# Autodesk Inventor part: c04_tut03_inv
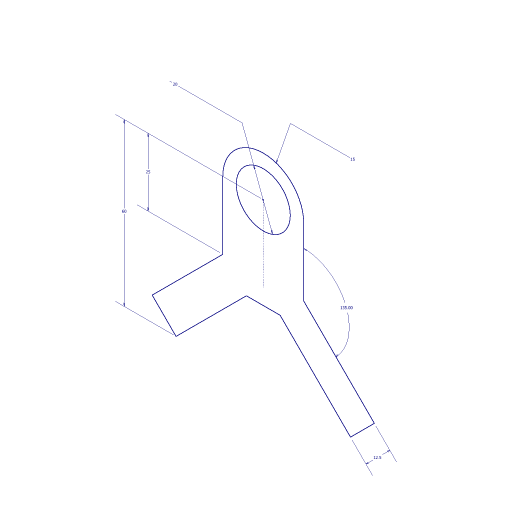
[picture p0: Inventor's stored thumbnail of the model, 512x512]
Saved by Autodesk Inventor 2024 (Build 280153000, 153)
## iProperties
Created: 2017-04
Part Number: c04_tut03_inv
Material: Generic
Document SubType Name: Modeling
Designer: CADCIM 00
Density: 1 g/cm^3
Appearance: Default
Author: CADCIM 00
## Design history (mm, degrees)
sketch "Sketch1"
  geometry: L1 (-6.25, -33.928)-(6.25, -33.928); L2 (6.25, -33.928)-(32.322, -60); L3 (32.322, -60)-(41.161, -51.161); L4 (41.161, -51.161)-(15, -25); L5 (15, -25)-(15, 0); L6 (-15, 0)-(-15, -25); L7 (-15, -25)-(-41.161, -51.161); L8 (-41.161, -51.161)-(-32.322, -60); L9 (-32.322, -60)-(-6.25, -33.928); L10 (0, 0)-(0, -28.219); C1 r 10 at (0, 0); A1 r 15 centre (0, 0) between (15, 0) and (-15, 0); 1 further point
  constraints: 20 end point, 5 perpendicular, 2 centre point, 2 coincident, 2 point on circle, 2 symmetric about line, 2 tangent, 1 concentric, 1 equal length, 1 horizontal, 1 parallel, 1 point on line, 1 vertical, 2 other
  dimensions: "d0" = 15 radius of A1; "d1" = 135 deg angle of L7 L6; "d2" = 12.5 distance of L7.end L8.end; "d3" = 60 vertical distance of L2.end L10.start; "d4" = 25 vertical distance of L10.start L4.end; "d5" = 20 diameter of C1
